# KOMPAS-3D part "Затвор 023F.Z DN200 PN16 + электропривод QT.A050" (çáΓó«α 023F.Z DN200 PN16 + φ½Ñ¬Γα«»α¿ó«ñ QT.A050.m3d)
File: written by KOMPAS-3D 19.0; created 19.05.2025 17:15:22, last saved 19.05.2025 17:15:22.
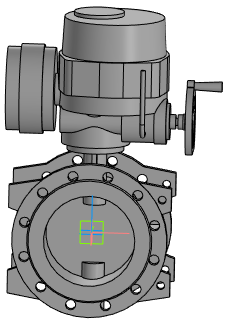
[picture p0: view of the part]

Document properties: Полное имя файла: Затвор 023F.Z DN200 PN16 + электропривод QT.A050.a3d

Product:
- Part/product: Затвор 023F.Z DN200 PN16 + электропривод QT.A050
    Масса: 155.802

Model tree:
1. Операция без истории:1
